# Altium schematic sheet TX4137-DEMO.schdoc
size A; SheetNumber: 0; SheetTotal: 0
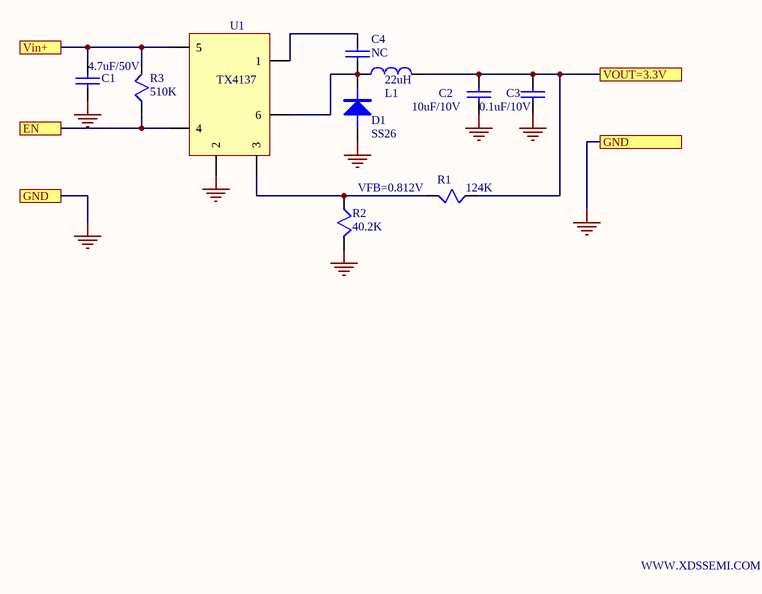
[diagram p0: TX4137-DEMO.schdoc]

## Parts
C1  4.7uF/50V  [R1206]
C2  10uF/10V  [0805C]
C3  0.1uF/10V  [0805C]
C4  NC  [0603]
D1  SS26  [SMA]
L1  22uH  [CD43]
R1  124K  [0603]
R2  40.2K  [0603]
R3  510K  [0603]
U1  TX4137

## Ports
EN, GND, Vin+, VOUT=3.3V

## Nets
GND: C1.1 C2.1 C3.1 D1.1(A) R2.2 U1.?3(2) ; port GND
EN: R3.1 U1.?2(4) ; port EN
Vin+: C1.2 R3.2 U1.?1(5) ; port Vin+
VOUT=3.3V: C2.2 C3.2 L1.2 R1.1 ; port VOUT=3.3V
NetC4_1: C4.1 U1.?5(1)
NetC4_2: C4.2 D1.2(K) L1.1 U1.?6(6)
NetR1_2: R1.2 R2.1 U1.?4(3)

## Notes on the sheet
- VFB=0.812V
- WWW.XDSSEMI.COM

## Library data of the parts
C1-C4 = CAP: Capacitor
D1 = DIODE
L1 = INDUCTOR
R1-R3 = RES1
